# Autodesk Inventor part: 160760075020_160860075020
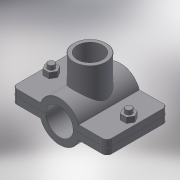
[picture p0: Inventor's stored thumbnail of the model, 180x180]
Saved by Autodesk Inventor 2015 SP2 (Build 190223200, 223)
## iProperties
Created: 2017-05
Part Number: 160760075020_160860075020
Material: Generic
Description: PLASSON SADDLE 75-2"
Document SubType Name: Modeling
Designer: KIM
Density: 1 g/cm^3
Appearance: Default
Author: KIM
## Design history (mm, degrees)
derived "16076.ipt"
feature "Solid1::16076.ipt"
feature "Solid2::16076.ipt"
tag "TaggingFeature1"
body "Solid1"
other parameters: "d0" = 93.75, "d1" = 122, "d2" = 37.5, "d3" = 75, "d4" = 98, "d5" = 0, "d6" = 6.1, "d7" = 122, "d8" = 0.1, "d10" = 0, "d11" = 0.75, "d14" = 73.6528, "d20" = 0.75, "d23" = 0.75, "d37" = 8, "d38" = 45.5, "d39" = 0, "d40" = 3, "d41" = 5, "d42" = 0, "d43" = 6, "d44" = 3, "d45" = 0, "d46" = 0.75, "d51" = 78, "d52" = 56.656, "d54" = 0, "d57" = 0, "d58" = 81, "d60" = 0, "d63" = 8, "d66" = 82, "d_" = 75, "G_" = 56.656, "A_" = 78, "L_" = 122, "L_1" = 98
